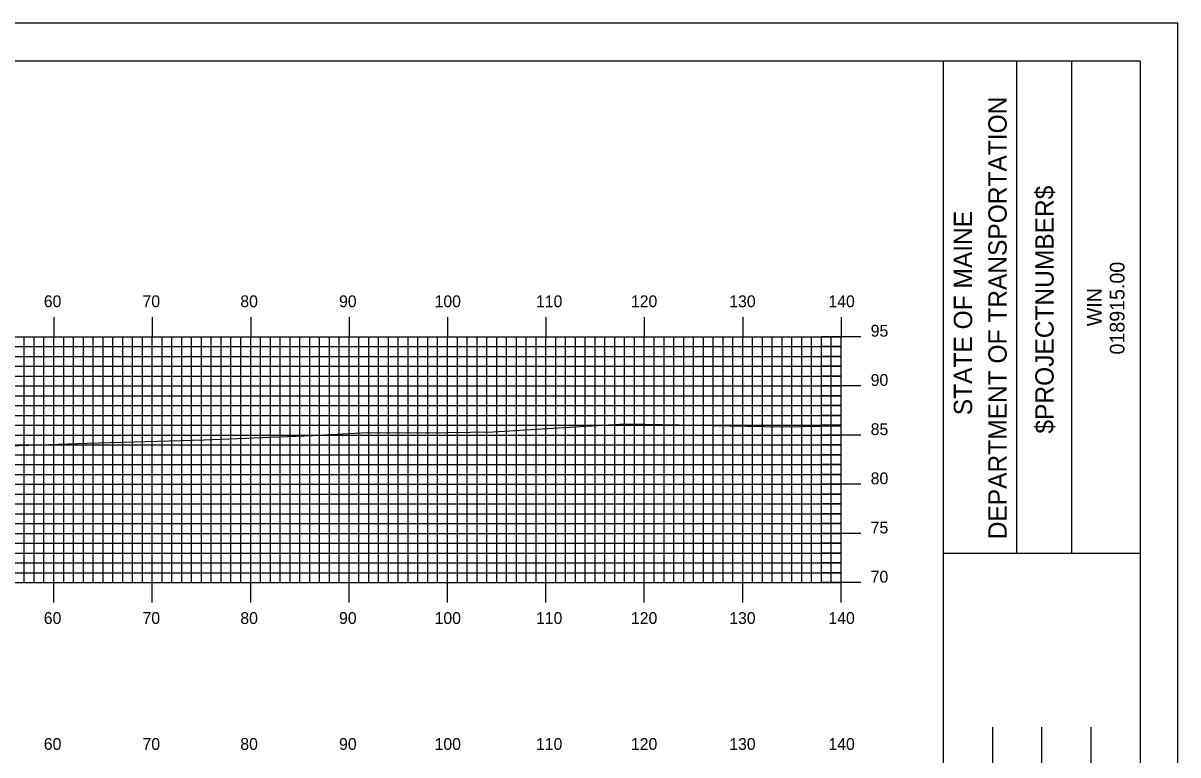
# Model space of a CAD drawing. Extents: x 1777138 to 1777481, y 442591 to 442811.
# Drawn here: x 1777360.6 to 1777478, y 442736.2 to 442810.5 of the extents above; entities that cross this region are included whole.
import ezdxf

# ---------------------------------------------------------------- set-up
doc = ezdxf.new("R2010")
doc.units = 0
for name, color, linetype in [('BORDER', 7, 'Continuous'), ('H_V ANNOTATION', 7, 'Continuous'), ('MAJOR', 7, 'Continuous'), ('MINOR', 7, 'Continuous'), ('PLOT BOUNDARY', 7, 'Continuous'), ('S_Roadway_Centerline', 7, 'Continuous')]:
    doc.layers.add(name, color=color, linetype=linetype)

msp = doc.modelspace()

# ---------------------------------------------------------------- linework, layer by layer
at = {"layer": 'BORDER'}
for p, q in [((1777454.16, 442596.67), (1777454.16, 442806.67)), ((1777461.62, 442756.66), (1777461.62, 442806.66)), ((1777467.21, 442756.66), (1777467.21, 442806.66)), ((1777454.17, 442756.65), (1777474.16, 442756.65)), ((1777459.16, 442721.67), (1777459.16, 442738.97)), ((1777464.16, 442721.67), (1777464.16, 442738.97)), ((1777469.16, 442721.67), (1777469.16, 442738.97))]:
    msp.add_line(p, q, dxfattribs=at)
msp.add_lwpolyline([(1777154.16, 442596.67), (1777474.16, 442596.67), (1777474.16, 442806.67), (1777154.16, 442806.67)], close=True, dxfattribs=at)
at = {"layer": 'MAJOR'}
for p, q in [((1777363.76, 442780.67), (1777363.76, 442778.67)), ((1777373.76, 442780.67), (1777373.76, 442778.67)), ((1777383.76, 442780.67), (1777383.76, 442778.67)), ((1777393.76, 442780.67), (1777393.76, 442778.67)), ((1777403.76, 442780.67), (1777403.76, 442778.67)), ((1777413.76, 442780.67), (1777413.76, 442778.67)), ((1777423.76, 442780.67), (1777423.76, 442778.67)), ((1777433.76, 442780.67), (1777433.76, 442778.67)), ((1777443.76, 442780.67), (1777443.76, 442778.67)), ((1777163.76, 442778.67), (1777443.76, 442778.67)), ((1777163.76, 442778.67), (1777443.76, 442778.67)), ((1777363.76, 442753.67), (1777363.76, 442778.67)), ((1777373.76, 442753.67), (1777373.76, 442778.67)), ((1777383.76, 442753.67), (1777383.76, 442778.67)), ((1777393.76, 442753.67), (1777393.76, 442778.67)), ((1777403.76, 442753.67), (1777403.76, 442778.67)), ((1777413.76, 442753.67), (1777413.76, 442778.67)), ((1777423.76, 442753.67), (1777423.76, 442778.67)), ((1777433.76, 442753.67), (1777433.76, 442778.67)), ((1777445.77, 442778.67), (1777441.76, 442778.67)), ((1777443.76, 442753.67), (1777443.76, 442778.67)), ((1777443.76, 442753.67), (1777443.76, 442778.67)), ((1777163.76, 442773.67), (1777443.76, 442773.67)), ((1777445.77, 442773.67), (1777441.76, 442773.67)), ((1777163.76, 442768.67), (1777443.76, 442768.67)), ((1777445.77, 442768.67), (1777441.76, 442768.67)), ((1777163.76, 442763.67), (1777443.76, 442763.67)), ((1777445.77, 442763.67), (1777441.76, 442763.67)), ((1777163.76, 442758.67), (1777443.76, 442758.67)), ((1777445.77, 442758.67), (1777441.76, 442758.67)), ((1777163.76, 442753.67), (1777443.76, 442753.67)), ((1777163.76, 442753.67), (1777443.76, 442753.67)), ((1777363.76, 442751.66), (1777363.76, 442753.67)), ((1777373.76, 442751.66), (1777373.76, 442753.67)), ((1777383.76, 442751.66), (1777383.76, 442753.67)), ((1777393.76, 442751.66), (1777393.76, 442753.67)), ((1777403.76, 442751.66), (1777403.76, 442753.67)), ((1777413.76, 442751.66), (1777413.76, 442753.67)), ((1777423.76, 442751.66), (1777423.76, 442753.67)), ((1777433.76, 442751.66), (1777433.76, 442753.67)), ((1777445.77, 442753.67), (1777441.76, 442753.67)), ((1777443.76, 442751.66), (1777443.76, 442753.67))]:
    msp.add_line(p, q, dxfattribs=at)
at = {"layer": 'MINOR'}
for p, q in [((1777360.76, 442753.67), (1777360.76, 442778.67)), ((1777361.76, 442753.67), (1777361.76, 442778.67)), ((1777362.76, 442753.67), (1777362.76, 442778.67)), ((1777364.76, 442753.67), (1777364.76, 442778.67)), ((1777365.76, 442753.67), (1777365.76, 442778.67)), ((1777366.76, 442753.67), (1777366.76, 442778.67)), ((1777367.76, 442753.67), (1777367.76, 442778.67)), ((1777368.76, 442753.67), (1777368.76, 442778.67)), ((1777369.76, 442753.67), (1777369.76, 442778.67)), ((1777370.76, 442753.67), (1777370.76, 442778.67)), ((1777371.76, 442753.67), (1777371.76, 442778.67)), ((1777372.76, 442753.67), (1777372.76, 442778.67)), ((1777374.76, 442753.67), (1777374.76, 442778.67)), ((1777375.76, 442753.67), (1777375.76, 442778.67)), ((1777376.76, 442753.67), (1777376.76, 442778.67)), ((1777377.76, 442753.67), (1777377.76, 442778.67)), ((1777378.76, 442753.67), (1777378.76, 442778.67)), ((1777379.76, 442753.67), (1777379.76, 442778.67)), ((1777380.76, 442753.67), (1777380.76, 442778.67)), ((1777381.76, 442753.67), (1777381.76, 442778.67)), ((1777382.76, 442753.67), (1777382.76, 442778.67)), ((1777384.76, 442753.67), (1777384.76, 442778.67)), ((1777385.76, 442753.67), (1777385.76, 442778.67)), ((1777386.76, 442753.67), (1777386.76, 442778.67)), ((1777387.76, 442753.67), (1777387.76, 442778.67)), ((1777388.76, 442753.67), (1777388.76, 442778.67)), ((1777389.76, 442753.67), (1777389.76, 442778.67)), ((1777390.76, 442753.67), (1777390.76, 442778.67)), ((1777391.76, 442753.67), (1777391.76, 442778.67)), ((1777392.76, 442753.67), (1777392.76, 442778.67)), ((1777394.76, 442753.67), (1777394.76, 442778.67)), ((1777395.76, 442753.67), (1777395.76, 442778.67)), ((1777396.76, 442753.67), (1777396.76, 442778.67)), ((1777397.76, 442753.67), (1777397.76, 442778.67)), ((1777398.76, 442753.67), (1777398.76, 442778.67)), ((1777399.76, 442753.67), (1777399.76, 442778.67)), ((1777400.76, 442753.67), (1777400.76, 442778.67)), ((1777401.76, 442753.67), (1777401.76, 442778.67)), ((1777402.76, 442753.67), (1777402.76, 442778.67)), ((1777404.76, 442753.67), (1777404.76, 442778.67)), ((1777405.76, 442753.67), (1777405.76, 442778.67)), ((1777406.76, 442753.67), (1777406.76, 442778.67)), ((1777407.76, 442753.67), (1777407.76, 442778.67)), ((1777408.76, 442753.67), (1777408.76, 442778.67)), ((1777409.76, 442753.67), (1777409.76, 442778.67)), ((1777410.76, 442753.67), (1777410.76, 442778.67)), ((1777411.76, 442753.67), (1777411.76, 442778.67)), ((1777412.76, 442753.67), (1777412.76, 442778.67)), ((1777414.76, 442753.67), (1777414.76, 442778.67)), ((1777415.76, 442753.67), (1777415.76, 442778.67)), ((1777416.76, 442753.67), (1777416.76, 442778.67)), ((1777417.76, 442753.67), (1777417.76, 442778.67)), ((1777418.76, 442753.67), (1777418.76, 442778.67)), ((1777419.76, 442753.67), (1777419.76, 442778.67)), ((1777420.76, 442753.67), (1777420.76, 442778.67)), ((1777421.76, 442753.67), (1777421.76, 442778.67)), ((1777422.76, 442753.67), (1777422.76, 442778.67)), ((1777424.76, 442753.67), (1777424.76, 442778.67)), ((1777425.76, 442753.67), (1777425.76, 442778.67)), ((1777426.76, 442753.67), (1777426.76, 442778.67)), ((1777427.76, 442753.67), (1777427.76, 442778.67)), ((1777428.76, 442753.67), (1777428.76, 442778.67)), ((1777429.76, 442753.67), (1777429.76, 442778.67)), ((1777430.76, 442753.67), (1777430.76, 442778.67)), ((1777431.76, 442753.67), (1777431.76, 442778.67)), ((1777432.76, 442753.67), (1777432.76, 442778.67)), ((1777434.76, 442753.67), (1777434.76, 442778.67)), ((1777435.76, 442753.67), (1777435.76, 442778.67)), ((1777436.76, 442753.67), (1777436.76, 442778.67)), ((1777437.76, 442753.67), (1777437.76, 442778.67)), ((1777438.76, 442753.67), (1777438.76, 442778.67)), ((1777439.76, 442753.67), (1777439.76, 442778.67)), ((1777440.76, 442753.67), (1777440.76, 442778.67)), ((1777441.76, 442753.67), (1777441.76, 442778.67)), ((1777442.76, 442753.67), (1777442.76, 442778.67)), ((1777163.76, 442777.67), (1777443.76, 442777.67)), ((1777443.76, 442777.67), (1777441.76, 442777.67)), ((1777163.76, 442776.67), (1777443.76, 442776.67)), ((1777443.76, 442776.67), (1777441.76, 442776.67)), ((1777163.76, 442775.67), (1777443.76, 442775.67)), ((1777443.76, 442775.67), (1777441.76, 442775.67)), ((1777163.76, 442774.67), (1777443.76, 442774.67)), ((1777443.76, 442774.67), (1777441.76, 442774.67)), ((1777163.76, 442772.67), (1777443.76, 442772.67)), ((1777443.76, 442772.67), (1777441.76, 442772.67)), ((1777163.76, 442771.67), (1777443.76, 442771.67)), ((1777443.76, 442771.67), (1777441.76, 442771.67)), ((1777163.76, 442770.67), (1777443.76, 442770.67)), ((1777443.76, 442770.67), (1777441.76, 442770.67)), ((1777163.76, 442769.67), (1777443.76, 442769.67)), ((1777443.76, 442769.67), (1777441.76, 442769.67)), ((1777163.76, 442767.67), (1777443.76, 442767.67)), ((1777163.76, 442766.67), (1777443.76, 442766.67)), ((1777443.76, 442767.67), (1777441.76, 442767.67)), ((1777443.76, 442766.67), (1777441.76, 442766.67)), ((1777163.76, 442765.67), (1777443.76, 442765.67)), ((1777443.76, 442765.67), (1777441.76, 442765.67)), ((1777163.76, 442764.67), (1777443.76, 442764.67)), ((1777443.76, 442764.67), (1777441.76, 442764.67)), ((1777163.76, 442762.67), (1777443.76, 442762.67)), ((1777443.76, 442762.67), (1777441.76, 442762.67)), ((1777163.76, 442761.67), (1777443.76, 442761.67)), ((1777443.76, 442761.67), (1777441.76, 442761.67)), ((1777163.76, 442760.67), (1777443.76, 442760.67)), ((1777163.76, 442759.67), (1777443.76, 442759.67)), ((1777443.76, 442760.67), (1777441.76, 442760.67)), ((1777443.76, 442759.67), (1777441.76, 442759.67)), ((1777163.76, 442757.67), (1777443.76, 442757.67)), ((1777443.76, 442757.67), (1777441.76, 442757.67)), ((1777163.76, 442756.67), (1777443.76, 442756.67)), ((1777443.76, 442756.67), (1777441.76, 442756.67)), ((1777163.76, 442755.67), (1777443.76, 442755.67)), ((1777443.76, 442755.67), (1777441.76, 442755.67)), ((1777163.76, 442754.67), (1777443.76, 442754.67)), ((1777443.76, 442754.67), (1777441.76, 442754.67))]:
    msp.add_line(p, q, dxfattribs=at)
at = {"layer": 'PLOT BOUNDARY'}
msp.add_lwpolyline([(1777137.98, 442590.55), (1777477.98, 442590.55), (1777477.98, 442810.55), (1777137.98, 442810.55)], close=True, dxfattribs=at)
at = {"layer": 'S_Roadway_Centerline'}
msp.add_lwpolyline([(1777356.27, 442767.47), (1777367.15, 442767.83), (1777379.04, 442768.17), (1777390.05, 442768.63), (1777395.61, 442768.93), (1777401.49, 442768.9), (1777408.4, 442768.99), (1777413.93, 442769.35), (1777421.81, 442769.8), (1777422.27, 442769.79), (1777423.84, 442769.78), (1777437.65, 442769.51), (1777443.76, 442769.61)], dxfattribs=at)

# ---------------------------------------------------------------- texts
at = {"layer": 'BORDER'}
for s, height, p in [('DEPARTMENT OF TRANSPORTATION', 1.8635, (1777460.58, 442758.08)), ('$PROJECTNUMBER$', 1.8635, (1777465.35, 442768.82)), ('STATE OF MAINE', 1.8635, (1777457.07, 442770.69)), ('018915.00', 1.491, (1777472.55, 442776.86)), ('WIN', 1.491, (1777470.24, 442779.73))]:
    msp.add_text(s, height=height, rotation=90, dxfattribs=at).set_placement(p)
at = {"layer": 'H_V ANNOTATION'}
for s, p in [('60', (1777362.74, 442781.67)), ('70', (1777372.77, 442781.67)), ('80', (1777382.71, 442781.67)), ('90', (1777392.74, 442781.67)), ('100', (1777402.45, 442781.67)), ('110', (1777412.75, 442781.67)), ('120', (1777422.4, 442781.67)), ('130', (1777432.39, 442781.67)), ('140', (1777442.47, 442781.67)), ('95', (1777446.76, 442778.67)), ('90', (1777446.76, 442773.67)), ('85', (1777446.76, 442768.67)), ('80', (1777446.76, 442763.67)), ('75', (1777446.76, 442758.67)), ('70', (1777446.76, 442753.67)), ('60', (1777362.74, 442749.47)), ('70', (1777372.77, 442749.47)), ('80', (1777382.71, 442749.47)), ('90', (1777392.74, 442749.47)), ('100', (1777402.45, 442749.47)), ('110', (1777412.75, 442749.47)), ('120', (1777422.4, 442749.47)), ('130', (1777432.39, 442749.47)), ('140', (1777442.47, 442749.47)), ('60', (1777362.74, 442736.67)), ('70', (1777372.77, 442736.67)), ('80', (1777382.71, 442736.67)), ('90', (1777392.74, 442736.67)), ('100', (1777402.45, 442736.67)), ('110', (1777412.75, 442736.67)), ('120', (1777422.4, 442736.67)), ('130', (1777432.39, 442736.67)), ('140', (1777442.47, 442736.67))]:
    msp.add_text(s, height=1.2, dxfattribs=at).set_placement(p)

doc.saveas('drawing.dxf')
